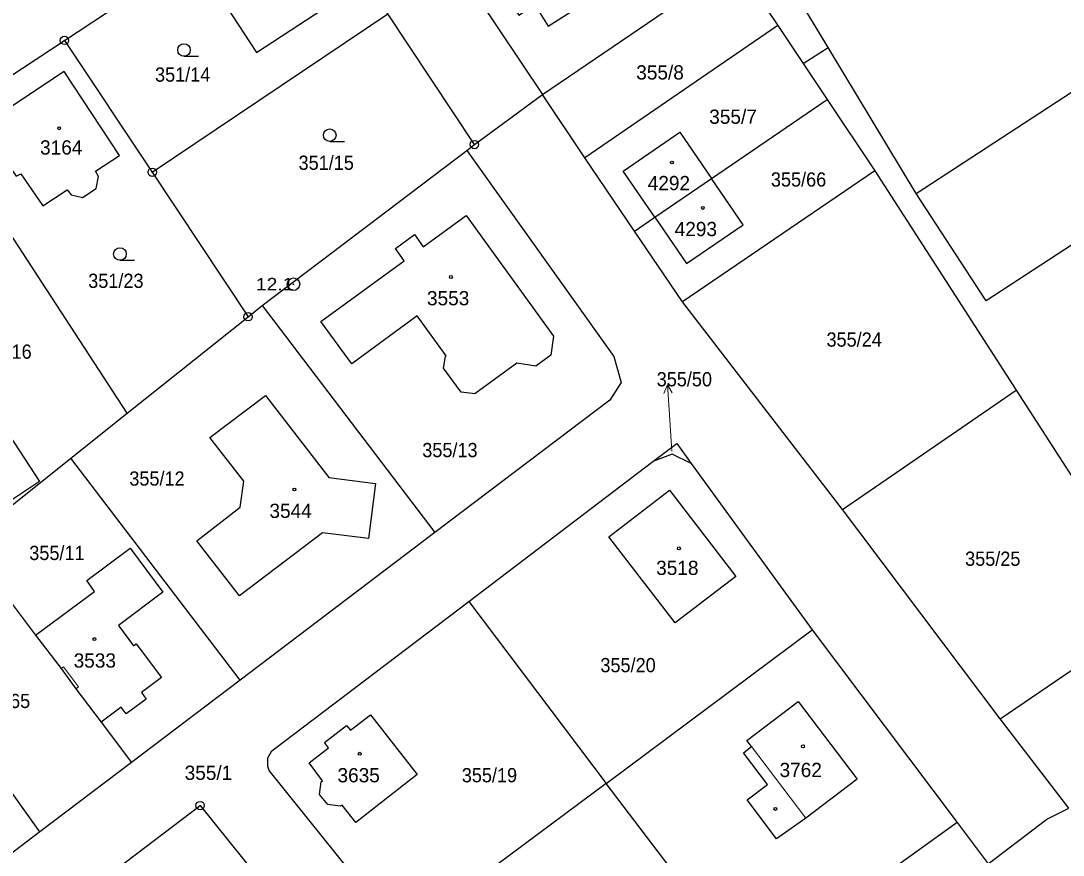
# Model space of a CAD drawing. Extents: x -679733 to -673243, y -1075091 to -1066557.
# Drawn here: x -675985.8 to -675861.3, y -1072766.7 to -1072667 of the extents above; entities that cross this region are included whole.
import ezdxf
from ezdxf.enums import TextEntityAlignment as Align

# ---------------------------------------------------------------- set-up
doc = ezdxf.new("R2010")
doc.units = 0
doc.header["$LTSCALE"] = 0.68
for name, color, linetype, lineweight in [('1', 7, 'Continuous', 25), ('3', 7, 'Continuous', 25), ('4', 7, 'Continuous', 13), ('5', 7, 'Continuous', 25), ('7', 7, 'Continuous', 13), ('8', 7, 'Continuous', 25)]:
    doc.layers.add(name, color=color, linetype=linetype, lineweight=lineweight)
doc.layers.add('2', color=7, linetype='Continuous')

msp = doc.modelspace()

# ---------------------------------------------------------------- linework, layer by layer
at = {"layer": '1'}
for p, q in [((-675895.36, -1072667.58), (-675918.44, -1072683.37)), ((-675878.83, -1072687.64), (-675847.47, -1072667.16)), ((-675980.59, -1072669.35), (-675970.1, -1072685.1)), ((-675892.33, -1072672.12), (-675889.34, -1072670.21)), ((-675931.61, -1072681.79), (-675923.48, -1072675.82)), ((-675918.44, -1072683.37), (-675923.48, -1072675.82)), ((-675883.79, -1072684.91), (-675906.75, -1072700.57)), ((-675910.05, -1072690.47), (-675903.3, -1072685.85)), ((-675912.49, -1072692.13), (-675910.05, -1072690.47)), ((-675956.96, -1072701), (-675936.33, -1072728.12)), ((-675973.08, -1072713.88), (-675958.65, -1072702.36)), ((-675887.64, -1072725.37), (-675866.89, -1072711.12)), ((-675959.58, -1072745.75), (-675979.83, -1072719.25)), ((-675992.34, -1072729.44), (-675984.03, -1072740.39)), ((-675983.52, -1072763.87), (-676002.33, -1072737.75)), ((-675868.82, -1072750.37), (-675849.89, -1072737.5)), ((-675959.58, -1072745.75), (-675972.59, -1072755.6)), ((-675976.2, -1072750.8), (-675972.59, -1072755.6)), ((-675972.59, -1072755.6), (-675983.52, -1072763.87)), ((-675873.94, -1072762.75), (-675898.76, -1072780.62))]:
    msp.add_line(p, q, dxfattribs=at)
for points in [[(-676027.21, -1072699.92), (-676010.49, -1072689.05), (-675995.68, -1072679.29), (-675980.59, -1072669.35), (-675952.24, -1072650.63), (-675943.9, -1072645.03), (-675920.42, -1072629.48)], [(-675889.34, -1072670.21), (-675895.49, -1072660.01), (-675865.07, -1072640.36), (-675858.4, -1072650.51)], [(-675883.79, -1072684.91), (-675866.89, -1072711.12), (-675849.89, -1072737.5), (-675844.82, -1072734.25), (-675821.51, -1072718.87), (-675793.88, -1072700.75), (-675830.26, -1072645.77)], [(-675970.1, -1072685.1), (-675941.94, -1072666.18), (-675952.24, -1072650.63)], [(-675933.75, -1072660.45), (-675923.48, -1072675.82), (-675900.4, -1072660.07)], [(-675900.4, -1072660.07), (-675895.36, -1072667.58), (-675892.33, -1072672.12)], [(-675970.1, -1072685.1), (-675958.65, -1072702.36), (-675956.96, -1072701), (-675932.52, -1072682.5), (-675931.61, -1072681.79), (-675941.94, -1072666.18)], [(-675847.47, -1072667.16), (-675839.57, -1072679.99), (-675849.4, -1072686.69), (-675841.4, -1072699.09), (-675820.99, -1072685.76), (-675814.27, -1072696.09), (-675820.97, -1072700.52), (-675818.2, -1072704.71), (-675821.84, -1072707.11), (-675824.6, -1072702.93), (-675834.87, -1072709.72), (-675831.37, -1072715.02), (-675841.76, -1072721.9), (-675860.16, -1072693.73), (-675870.46, -1072700.46), (-675878.83, -1072687.64), (-675889.34, -1072670.21)], [(-675892.33, -1072672.12), (-675889.46, -1072676.41), (-675883.79, -1072684.91)], [(-675910.05, -1072690.47), (-675913.83, -1072684.95), (-675907.09, -1072680.32), (-675903.3, -1072685.85), (-675889.46, -1072676.41)], [(-675986.82, -1072724.85), (-675979.83, -1072719.25), (-675973.08, -1072713.88), (-675995.68, -1072679.29)], [(-675932.52, -1072682.5), (-675914.95, -1072707.09), (-675914.07, -1072710.21), (-675915.43, -1072712.32), (-675936.33, -1072728.12), (-675959.58, -1072745.75)], [(-675906.75, -1072700.57), (-675912.49, -1072692.13), (-675918.44, -1072683.37)], [(-675910.05, -1072690.47), (-675906.28, -1072696), (-675899.5, -1072691.39), (-675903.3, -1072685.85)], [(-675870.24, -1072767.69), (-675863.22, -1072762.39), (-675860.6, -1072761.04), (-675868.82, -1072750.37), (-675887.64, -1072725.37), (-675906.75, -1072700.57)], [(-675910.28, -1072719.65), (-675907.45, -1072717.5), (-675905.73, -1072719.87), (-675891.26, -1072739.75), (-675873.94, -1072762.75), (-675870.24, -1072767.69)], [(-675905.73, -1072719.87), (-675907.99, -1072718.77), (-675910.28, -1072719.65)], [(-675940.27, -1072776.25), (-675956.15, -1072756.56), (-675956.3, -1072756.05), (-675956.31, -1072755.06), (-675955.81, -1072754.19), (-675932.27, -1072736.37), (-675910.28, -1072719.65)], [(-675984.03, -1072740.39), (-675977, -1072735.16), (-675977.92, -1072733.88), (-675972.72, -1072730.01), (-675968.82, -1072735.26), (-675974.14, -1072739.24), (-675972.33, -1072741.67), (-675972.02, -1072741.44), (-675969.01, -1072745.44), (-675971.38, -1072747.24), (-675970.83, -1072748.03), (-675973.22, -1072749.79), (-675973.82, -1072749), (-675976.2, -1072750.8)], [(-675932.27, -1072736.37), (-675915.89, -1072758.12), (-675891.26, -1072739.75)], [(-675984.03, -1072740.39), (-675981, -1072744.38), (-675979.21, -1072746.79), (-675976.2, -1072750.8)], [(-675922.19, -1072797.5), (-675898.76, -1072780.62), (-675915.89, -1072758.12), (-675940.27, -1072776.25)], [(-675981.91, -1072774.03), (-675964.38, -1072760.75), (-675943.33, -1072786.91)], [(-675983.52, -1072763.87), (-676004.71, -1072780), (-676000.64, -1072785), (-675998.21, -1072786.5), (-675981.91, -1072774.03)]]:
    msp.add_lwpolyline(points, dxfattribs=at)
for points in [[(-675919.23, -1072661.76), (-675924.07, -1072654.23), (-675931.12, -1072658.82), (-675926.31, -1072666.34), (-675924.41, -1072665.11), (-675922.79, -1072667.64), (-675917.6, -1072664.3)], [(-675951.21, -1072661.04), (-675949.65, -1072660.02), (-675952.98, -1072654.84), (-675963.55, -1072661.76), (-675957.65, -1072670.8), (-675948.68, -1072664.94)], [(-675986.37, -1072685.58), (-675985.81, -1072685.27), (-675983.17, -1072689.12), (-675980.27, -1072687.2), (-675979.79, -1072687.8), (-675978.43, -1072688.11), (-675976.79, -1072687.03), (-675976.53, -1072685.62), (-675976.88, -1072684.97), (-675974, -1072683.11), (-675980.64, -1072673.07), (-675989.69, -1072679.06), (-675987.32, -1072682.8), (-675987.99, -1072683.22)], [(-675946.26, -1072707.98), (-675949.95, -1072702.92), (-675940, -1072695.66), (-675941.06, -1072694.21), (-675938.78, -1072692.54), (-675937.72, -1072693.99), (-675932.59, -1072690.25), (-675922.15, -1072704.67), (-675922.5, -1072706.94), (-675924.28, -1072708.27), (-675926.56, -1072707.92), (-675931.58, -1072711.57), (-675933.18, -1072711.35), (-675935.31, -1072708.5), (-675935.08, -1072707.1), (-675934.98, -1072707.01), (-675938.45, -1072702.23)], [(-675944.27, -1072728.86), (-675949.78, -1072728.16), (-675959.67, -1072735.71), (-675964.76, -1072729.12), (-675959.59, -1072725.09), (-675959.16, -1072722), (-675963.21, -1072716.78), (-675956.59, -1072711.77), (-675949, -1072721.56), (-675943.43, -1072722.27)], [(-675983.58, -1072722.05), (-675986.91, -1072724.25), (-675992.97, -1072715.09), (-675989.59, -1072712.86)], [(-675908.29, -1072723.08), (-675900.4, -1072733.38), (-675907.63, -1072738.93), (-675915.54, -1072728.64)], [(-675885.9, -1072757.61), (-675892.03, -1072762.27), (-675895.52, -1072764.72), (-675899.03, -1072760.07), (-675896.6, -1072758.24), (-675899.47, -1072754.44), (-675898.51, -1072753.71), (-675899.08, -1072752.96), (-675892.95, -1072748.33)], [(-675946.4, -1072751.73), (-675944.03, -1072749.89), (-675938.45, -1072757.02), (-675945.79, -1072762.76), (-675947.4, -1072760.68), (-675947.66, -1072760.8), (-675949.14, -1072760.61), (-675950.11, -1072759.42), (-675949.92, -1072757.91), (-675949.76, -1072757.78), (-675951.37, -1072755.65), (-675949.04, -1072753.83), (-675949.51, -1072753.22), (-675946.89, -1072751.18)]]:
    msp.add_lwpolyline(points, close=True, dxfattribs=at)
at = {"layer": '3'}
for p, q in [((-675966.313, -1072671.24), (-675964.563, -1072671.24)), ((-675948.893, -1072681.41), (-675947.143, -1072681.41)), ((-675973.963, -1072695.61), (-675972.213, -1072695.61))]:
    msp.add_line(p, q, dxfattribs=at)
for centre in [(-675966.3129, -1072670.4898), (-675948.8929, -1072680.6598), (-675973.9629, -1072694.8598)]:
    msp.add_circle(centre, 0.75, dxfattribs=at)
at = {"layer": '4'}
for p, q in [((-675981, -1072744.38), (-675980.7, -1072744.16)), ((-675898.51, -1072753.71), (-675892.03, -1072762.27))]:
    msp.add_line(p, q, dxfattribs=at)
msp.add_lwpolyline([(-675980.7, -1072744.16), (-675978.9, -1072746.56), (-675979.21, -1072746.79)], dxfattribs=at)
at = {"layer": '5'}
for centre in [(-675981.2168, -1072679.8392), (-675908.0168, -1072683.9292), (-675904.3268, -1072689.3592), (-675934.4168, -1072697.6092), (-675953.1168, -1072722.9892), (-675907.1868, -1072730.0192), (-675977.0068, -1072740.8592), (-675892.3568, -1072753.6692), (-675945.3068, -1072754.5592), (-675895.6568, -1072761.1492)]:
    msp.add_circle(centre, 0.175, dxfattribs=at)
at = {"layer": '7'}
msp.add_line((-675908.539, -1072710.496), (-675908.969, -1072711.53), dxfattribs=at)
msp.add_lwpolyline([(-675908.02, -1072718.42), (-675908.33, -1072713.49), (-675908.539, -1072710.496), (-675907.97, -1072711.46)], dxfattribs=at)
at = {"layer": '8'}
for centre, radius in [((-675980.59, -1072669.3499), 0.5), ((-675980.59, -1072669.3499), 0.0303), ((-675931.61, -1072681.7899), 0.5), ((-675931.61, -1072681.7899), 0.0303), ((-675970.1, -1072685.0999), 0.5), ((-675970.1, -1072685.0999), 0.0303), ((-675953.23, -1072698.4698), 0.75), ((-675953.23, -1072698.4698), 0.03), ((-675958.65, -1072702.3599), 0.5), ((-675958.65, -1072702.3599), 0.0303), ((-675964.38, -1072760.7499), 0.5), ((-675964.38, -1072760.7499), 0.0303)]:
    msp.add_circle(centre, radius, dxfattribs=at)

# ---------------------------------------------------------------- texts
at = {"layer": '2', "width": 0.95}
for s, p in [('351/14', (-675969.77, -1072674.279)), ('351/15', (-675952.62, -1072684.81)), ('351/23', (-675977.75, -1072698.91)), ('355/24', (-675889.55, -1072705.93)), ('351/16', (-675991.11, -1072707.37)), ('355/13', (-675937.84, -1072719.13)), ('355/12', (-675972.84, -1072722.529)), ('355/11', (-675984.79, -1072731.42)), ('355/25', (-675872.99, -1072732.11)), ('355/20', (-675916.56, -1072744.82)), ('355/19', (-675933.12, -1072757.97))]:
    msp.add_text(s, height=1.7, dxfattribs=at).set_placement(p)
at = {"layer": '2'}
for s, p in [('355/8', (-675912.28, -1072674.019)), ('355/7', (-675903.56, -1072679.31)), ('3164', (-675983.5, -1072682.979)), ('3553', (-675937.28, -1072700.989)), ('3544', (-675956.1, -1072726.39)), ('3518', (-675909.9, -1072733.2)), ('3533', (-675979.49, -1072744.269)), ('355/1', (-675966.23, -1072757.68)), ('3635', (-675947.97, -1072757.97)), ('3762', (-675895.16, -1072757.34))]:
    msp.add_text(s, height=1.7, dxfattribs=at).set_placement(p)
for s, p in [('4292', (-675908.38, -1072687.239)), ('4293', (-675905.16, -1072692.729))]:
    msp.add_text(s, height=1.7, dxfattribs=at).set_placement(p, align=Align.CENTER)
at = {"layer": '2', "width": 0.95}
for s, p in [('355/66', (-675892.889, -1072686.81)), ('355/65', (-675987.989, -1072749.1))]:
    msp.add_text(s, height=1.7, dxfattribs=at).set_placement(p, align=Align.CENTER)
msp.add_text('355/50', height=1.7, dxfattribs=at).set_placement((-675903.23, -1072710.67), align=Align.RIGHT)
at = {"layer": '8', "width": 1.15}
msp.add_text('12.1', height=1.5, dxfattribs=at).set_placement((-675953.23, -1072699.22), align=Align.RIGHT)

doc.saveas('drawing.dxf')
